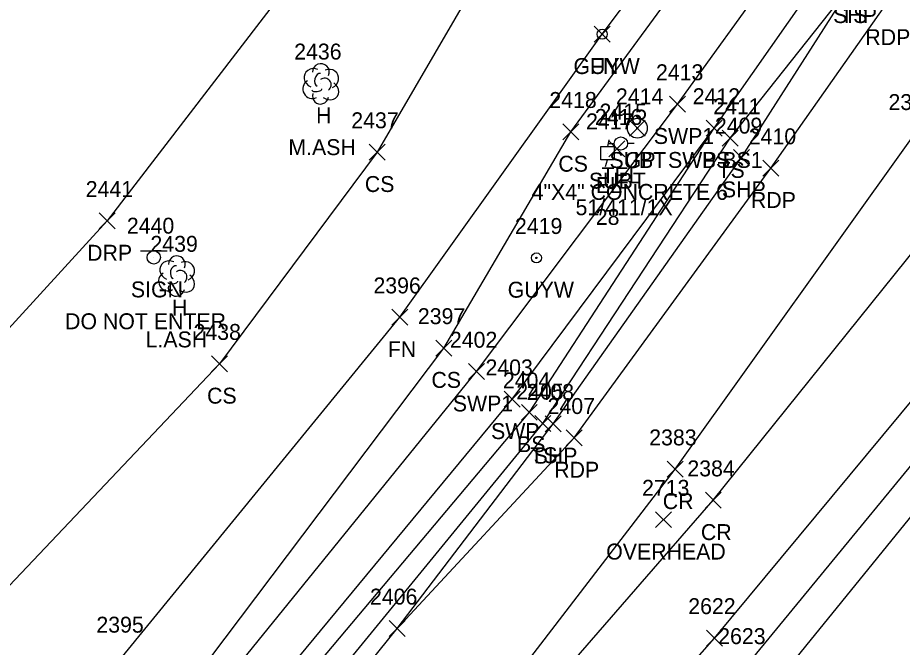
# Model space of a CAD drawing. Extents: x 1477930 to 1480780, y 774090 to 784647.
# Drawn here: x 1479285.9 to 1479397, y 774778.8 to 774857.9 of the extents above; entities that cross this region are included whole.
import ezdxf

# ---------------------------------------------------------------- set-up
doc = ezdxf.new("R2010")
doc.units = 0
for name, color, linetype in [('L_A', 7, 'Continuous'), ('L_C', 7, 'Continuous'), ('L_I', 7, 'Continuous'), ('L_TIC', 7, 'Continuous'), ('LELB', 7, 'Continuous'), ('LFNC', 7, 'Continuous'), ('LTD', 7, 'Continuous'), ('P_A', 7, 'Continuous'), ('P_I', 7, 'Continuous'), ('P_TIC', 7, 'Continuous'), ('PET', 7, 'Continuous'), ('PRC', 7, 'Continuous'), ('PSP', 7, 'Continuous'), ('R_A', 7, 'Continuous'), ('R_C', 7, 'Continuous'), ('R_I', 7, 'Continuous'), ('R_TIC', 7, 'Continuous'), ('RDP', 7, 'Continuous'), ('RGP', 7, 'Continuous'), ('RSW', 7, 'Continuous'), ('S_A', 7, 'Continuous'), ('S_C', 7, 'Continuous'), ('S_I', 7, 'Continuous'), ('SSGN', 7, 'Continuous'), ('U_A', 7, 'Continuous'), ('U_C', 7, 'Continuous'), ('U_I', 7, 'Continuous'), ('U_TIC', 7, 'Continuous'), ('UEPT', 7, 'Continuous'), ('UP', 7, 'Continuous'), ('UPGW', 7, 'Continuous')]:
    doc.layers.add(name, color=color, linetype=linetype)

msp = doc.modelspace()

# ---------------------------------------------------------------- linework, layer by layer
at = {"layer": 'L_TIC'}
for points in [[(1479358.32, 774854.82), (1479360.32, 774856.82)], [(1479360.32, 774854.82), (1479358.32, 774856.82)], [(1479372.39, 774843.03), (1479374.39, 774845.03)], [(1479374.39, 774843.03), (1479372.39, 774845.03)], [(1479354.38, 774842.56), (1479356.38, 774844.56)], [(1479356.38, 774842.56), (1479354.38, 774844.56)], [(1479374.4, 774841.78), (1479376.4, 774843.78)], [(1479376.4, 774841.78), (1479374.4, 774843.78)], [(1479330.08, 774840.01), (1479332.08, 774842.01)], [(1479332.08, 774840.01), (1479330.08, 774842.01)], [(1479332.92, 774819.28), (1479334.92, 774821.28)], [(1479334.92, 774819.28), (1479332.92, 774821.28)], [(1479338.44, 774815.42), (1479340.44, 774817.42)], [(1479340.44, 774815.42), (1479338.44, 774817.42)], [(1479310.27, 774813.44), (1479312.27, 774815.44)], [(1479312.27, 774813.44), (1479310.27, 774815.44)], [(1479349.18, 774807.35), (1479351.18, 774809.35)], [(1479351.18, 774807.35), (1479349.18, 774809.35)], [(1479350.88, 774805.96), (1479352.88, 774807.96)], [(1479352.88, 774805.96), (1479350.88, 774807.96)]]:
    msp.add_lwpolyline(points, dxfattribs=at)
at = {"layer": 'LELB'}
for points in [[(1479359.96, 774879.16), (1479348.06, 774870.2), (1479331.08, 774841.01), (1479311.27, 774814.44), (1479269.72, 774770.63), (1479258.46, 774742.87), (1479189.67, 774702.56), (1479160.61, 774665.86)], [(1478962.33, 774641.76), (1478963.97, 774605.71), (1478989.2, 774585.18), (1479035.48, 774565.64), (1479062.1, 774571.6), (1479071.52, 774575.06), (1479101.02, 774601.1), (1479154.98, 774641.54), (1479197.13, 774670.38), (1479247.47, 774711.89), (1479280.68, 774743.82), (1479306.08, 774772.18), (1479339.44, 774816.42), (1479355.38, 774843.56), (1479373.73, 774868.57)], [(1478740.27, 774421.37), (1478804.49, 774448.68), (1478839.51, 774461.41), (1478900.12, 774482.9), (1478933.76, 774495.55), (1478952.86, 774503.55), (1479014.49, 774533.68), (1479069.06, 774560.68), (1479112.01, 774585.56), (1479167.75, 774622.17), (1479210.47, 774656.8), (1479257.79, 774698.97), (1479291.85, 774733.88), (1479316.96, 774764.31), (1479351.88, 774806.96), (1479375.4, 774842.78), (1479390.8, 774862.22)], [(1479239.1, 774628.15), (1479242.92, 774638.24), (1479276.86, 774668.3), (1479306.94, 774697.73), (1479319.53, 774710.27), (1479351.31, 774740.09), (1479380.37, 774773.44), (1479412.56, 774813.05), (1479431.34, 774845.03)], [(1479014.49, 774533.68), (1479043.28, 774555.25), (1479065.32, 774566.41), (1479074.11, 774570.76), (1479108.86, 774587.86), (1479163.89, 774628.29), (1479207.81, 774659.29), (1479255.33, 774701.37), (1479289.44, 774735.89), (1479314.43, 774765.82), (1479350.18, 774808.35), (1479373.39, 774844.03)]]:
    msp.add_lwpolyline(points, dxfattribs=at)
at = {"layer": 'LFNC'}
msp.add_lwpolyline([(1478963.8, 774657.83), (1478978.61, 774653.25), (1478971.45, 774628.81), (1478963.97, 774605.71), (1479000.4, 774593.85), (1479046.12, 774579.13), (1479053.93, 774576.72), (1479097.31, 774607.25), (1479152.18, 774645.44), (1479192.1, 774673.94), (1479241.74, 774716.53), (1479274.15, 774749.58), (1479299.07, 774777.69), (1479333.92, 774820.28), (1479359.32, 774855.82), (1479370.21, 774870.3)], dxfattribs=at)
at = {"layer": 'LTD'}
for p, q in [((1479323.97, 774849.64), (1479323.97, 774849.64)), ((1479323.97, 774849.64), (1479323.97, 774849.64)), ((1479305.86, 774825.5), (1479305.86, 774825.5)), ((1479305.86, 774825.5), (1479305.86, 774825.5))]:
    msp.add_line(p, q, dxfattribs=at)
for centre in [(1479324.01, 774851.07), (1479305.91, 774826.93)]:
    msp.add_arc(centre, 1.05, 335.5272, 180.9563, dxfattribs=at)
for centre, major_axis, ratio, start_param, end_param in [((1479323.18, 774850.3), (1.21, -0.51), 0.895232, 1.570796, 4.712389), ((1479325.01, 774850.22), (-1.14, -0.48), 0.949671, 1.570796, 4.712389), ((1479323.76, 774850.09), (-0.208, -0.792), 0.645439, 3.141593, 6.283185), ((1479324.47, 774849.47), (-0.5, 0.667), 0.989748, 3.141593, 6.283185), ((1479322.88, 774848.93), (0.58, -1.04), 0.959034, 3.141593, 6.283185), ((1479324.97, 774848.8), (-1.09, 0.79), 0.841452, 1.570796, 4.712389), ((1479323.97, 774848.14), (0.26, 1.06), 0.942809, 1.570796, 4.712389), ((1479323.51, 774848.89), (-0.625, -0.083), 0.423636, 0, 3.141593), ((1479305.07, 774826.16), (1.21, -0.51), 0.895232, 1.570796, 4.712389), ((1479306.9, 774826.08), (-1.14, -0.48), 0.949671, 1.570796, 4.712389), ((1479304.78, 774824.79), (0.58, -1.04), 0.959034, 3.141593, 6.283185), ((1479305.65, 774825.96), (-0.208, -0.792), 0.645439, 3.141593, 6.283185), ((1479306.36, 774825.33), (-0.5, 0.667), 0.989748, 3.141593, 6.283185), ((1479305.41, 774824.75), (-0.625, -0.083), 0.423636, 0, 3.141593), ((1479306.86, 774824.66), (-1.09, 0.79), 0.841452, 1.570796, 4.712389), ((1479305.86, 774824), (0.26, 1.06), 0.942809, 1.570796, 4.712389)]:
    msp.add_ellipse(centre, major_axis=major_axis, ratio=ratio, start_param=start_param, end_param=end_param, dxfattribs=at)
at = {"layer": 'P_TIC'}
for points in [[(1479375.82, 774839.34), (1479377.82, 774841.34)], [(1479377.82, 774839.34), (1479375.82, 774841.34)], [(1479379.51, 774838), (1479381.51, 774840)], [(1479381.51, 774838), (1479379.51, 774840)], [(1479352.18, 774805.91), (1479354.18, 774807.91)], [(1479354.18, 774805.91), (1479352.18, 774807.91)], [(1479354.81, 774804.14), (1479356.81, 774806.14)], [(1479356.81, 774804.14), (1479354.81, 774806.14)], [(1479367.49, 774800.2), (1479369.49, 774802.2)], [(1479369.49, 774800.2), (1479367.49, 774802.2)], [(1479372.28, 774796.31), (1479374.28, 774798.31)], [(1479374.28, 774796.31), (1479372.28, 774798.31)], [(1479332.57, 774780.21), (1479334.57, 774782.21)], [(1479334.57, 774780.21), (1479332.57, 774782.21)], [(1479332.57, 774780.21), (1479334.57, 774782.21)], [(1479334.57, 774780.21), (1479332.57, 774782.21)], [(1479372.44, 774779.01), (1479374.44, 774781.01)], [(1479374.44, 774779.01), (1479372.44, 774781.01)]]:
    msp.add_lwpolyline(points, dxfattribs=at)
at = {"layer": 'PET'}
for points in [[(1479231.31, 774636.06), (1479272.54, 774672.78), (1479302.99, 774702.6), (1479344.22, 774746.86), (1479373.44, 774780.01), (1479405.23, 774818.27), (1479428.23, 774848.68), (1479447.93, 774875.75), (1479460.71, 774894.51), (1479479.69, 774925.18), (1479480.31, 774927.38), (1479493.45, 774951.2), (1479514.74, 775006.53), (1479531.7, 775055.13), (1479548.14, 775106.72), (1479553.83, 775125.43), (1479564.45, 775161.29), (1479573.74, 775193.3), (1479576.58, 775204.25), (1479585.43, 775238.68), (1479593.96, 775273.34), (1479599.4, 775295.6)], [(1479168.73, 774620.31), (1479212.4, 774655.38), (1479259.7, 774697.56), (1479293.15, 774732.73), (1479318.8, 774762.89), (1479333.57, 774781.21), (1479355.81, 774805.14), (1479380.51, 774839), (1479394.88, 774859.45), (1479419.72, 774898.43), (1479440.51, 774934.48), (1479462.36, 774978.06), (1479482.36, 775026.15), (1479497.52, 775065.91), (1479509.28, 775100.79), (1479510.93, 775118.31)]]:
    msp.add_lwpolyline(points, dxfattribs=at)
at = {"layer": 'PRC'}
for points in [[(1479194.24, 774620.68), (1479224.8, 774645.46), (1479270.23, 774685.77), (1479304.81, 774721.63), (1479337.5, 774760.88), (1479368.49, 774801.2), (1479398.58, 774843.3), (1479429.86, 774889.66)], [(1479304.81, 774721.63), (1479339.94, 774758.98), (1479373.28, 774797.31), (1479405.3, 774837.12), (1479437.9, 774882.86)]]:
    msp.add_lwpolyline(points, dxfattribs=at)
at = {"layer": 'PSP'}
for points in [[(1479333.57, 774781.21), (1479353.18, 774806.91), (1479376.82, 774840.34), (1479390.8, 774862.22), (1479415.7, 774900.26), (1479436.53, 774936.29), (1479458.59, 774979.44), (1479478.64, 775027.16), (1479495.22, 775066.68), (1479506.41, 775101.31), (1479509.16, 775114.37), (1479508.43, 775127.01)], [(1479234.45, 774632.83), (1479231.31, 774636.06), (1479275.79, 774669.49), (1479305.63, 774698.93), (1479347.8, 774743.57), (1479377.2, 774776.25), (1479409.48, 774815.47), (1479431.34, 774845.03), (1479437.58, 774844.49), (1479438.63, 774843.63)]]:
    msp.add_lwpolyline(points, dxfattribs=at)
at = {"layer": 'R_TIC'}
for points in [[(1479367.77, 774846.04), (1479369.77, 774848.04)], [(1479369.77, 774846.04), (1479367.77, 774848.04)], [(1479372.39, 774843.03), (1479374.39, 774845.03)], [(1479374.39, 774843.03), (1479372.39, 774845.03)], [(1479296.16, 774831.38), (1479298.16, 774833.38)], [(1479298.16, 774831.38), (1479296.16, 774833.38)], [(1479342.53, 774812.46), (1479344.53, 774814.46)], [(1479344.53, 774812.46), (1479342.53, 774814.46)], [(1479347.01, 774808.99), (1479349.01, 774810.99)], [(1479349.01, 774808.99), (1479347.01, 774810.99)]]:
    msp.add_lwpolyline(points, dxfattribs=at)
at = {"layer": 'RDP'}
msp.add_lwpolyline([(1479339.32, 774894.51), (1479323.7, 774866.97), (1479297.16, 774832.38), (1479261.24, 774793.14), (1479230.98, 774760.26), (1479216.66, 774770.36), (1479214.83, 774766.86), (1479218.05, 774749.14), (1479185.32, 774759.37)], dxfattribs=at)
at = {"layer": 'RGP'}
msp.add_line((1479363.74, 774844.02), (1479363.74, 774844.02), dxfattribs=at)
for radius in [1.25, 0.0833]:
    msp.add_circle((1479363.74, 774844.02), radius, dxfattribs=at)
at = {"layer": 'RSW'}
for points in [[(1479274.17, 774731.39), (1479308.42, 774770.17), (1479343.53, 774813.46), (1479368.77, 774847.04), (1479380.89, 774863.8), (1479383.37, 774867.44), (1479386.24, 774871.51), (1479407.11, 774905.13), (1479428.53, 774941.71), (1479450.08, 774982.66), (1479469.96, 775030.3), (1479484.01, 775070.5), (1479497.13, 775105.7)], [(1479277.58, 774728.25), (1479312.53, 774767.11), (1479348.01, 774809.99), (1479373.39, 774844.03), (1479387.54, 774864.22), (1479390.19, 774868.27), (1479411.38, 774902.61), (1479432.83, 774938.99), (1479454.5, 774980.05), (1479474.41, 775028.7), (1479489.03, 775068.75), (1479501.66, 775103.93)]]:
    msp.add_lwpolyline(points, dxfattribs=at)
at = {"layer": 'SSGN'}
for p, q in [((1479301.36, 774828.63), (1479304.69, 774828.63)), ((1479303.01, 774827.8), (1479303.01, 774827.8))]:
    msp.add_line(p, q, dxfattribs=at)
msp.add_circle((1479303.01, 774827.8), 0.833, dxfattribs=at)
at = {"layer": 'U_TIC'}
for points in [[(1479362.74, 774843.02), (1479364.74, 774845.02)], [(1479364.74, 774843.02), (1479362.74, 774845.02)], [(1479360.16, 774840.43), (1479362.16, 774842.43)], [(1479362.16, 774840.43), (1479360.16, 774842.43)], [(1479366.02, 774793.87), (1479368.02, 774795.87)], [(1479368.02, 774793.87), (1479366.02, 774795.87)]]:
    msp.add_lwpolyline(points, dxfattribs=at)
at = {"layer": 'UEPT'}
for p, q in [((1479360.16, 774842.54), (1479359.99, 774841.71)), ((1479359.16, 774840.04), (1479359.16, 774841.71)), ((1479359.16, 774841.71), (1479360.82, 774841.71)), ((1479360.82, 774841.71), (1479360.82, 774840.04)), ((1479359.99, 774840.88), (1479359.99, 774840.88)), ((1479360.82, 774840.04), (1479359.16, 774840.04)), ((1479359.74, 774839.21), (1479359.99, 774840.04))]:
    msp.add_line(p, q, dxfattribs=at)
at = {"layer": 'UP'}
for p, q in [((1479360.02, 774842.1), (1479360.85, 774842.1)), ((1479361.68, 774842.1), (1479361.68, 774842.1)), ((1479363.35, 774842.1), (1479362.52, 774842.1)), ((1479362.52, 774842.1), (1479362.52, 774842.1)), ((1479363.35, 774842.1), (1479363.35, 774842.1))]:
    msp.add_line(p, q, dxfattribs=at)
msp.add_circle((1479361.68, 774842.1), 0.833, dxfattribs=at)
at = {"layer": 'UPGW'}
for centre, radius in [((1479359.32, 774855.82), 0.625), ((1479359.32, 774855.82), 0.0833), ((1479351.07, 774827.74), 0.625), ((1479351.07, 774827.74), 0.0833)]:
    msp.add_circle(centre, radius, dxfattribs=at)

# ---------------------------------------------------------------- texts
at = {"layer": 'L_A'}
for s, p in [('TS', (1479389.21, 774857.22)), ('FN', (1479357.8, 774850.82)), ('H', (1479323.4, 774844.64)), ('CS', (1479353.82, 774838.56)), ('BS', (1479371.83, 774839.03)), ('TS', (1479373.81, 774837.78)), ('CS', (1479329.52, 774836.01)), ('H', (1479305.3, 774820.5)), ('FN', (1479332.4, 774815.28)), ('CS', (1479337.88, 774811.42)), ('CS', (1479309.71, 774809.44)), ('BS', (1479348.63, 774803.35)), ('TS', (1479350.29, 774801.96))]:
    msp.add_text(s, height=2, dxfattribs=at).set_placement(p)
at = {"layer": 'L_C'}
for s, p in [('M.ASH', (1479319.92, 774840.64)), ('L.ASH', (1479301.99, 774816.5))]:
    msp.add_text(s, height=2, dxfattribs=at).set_placement(p)
at = {"layer": 'L_I'}
for s, p in [('2436', (1479320.65, 774852.64)), ('2418', (1479352.69, 774846.56)), ('2412', (1479370.69, 774847.03)), ('2411', (1479373.27, 774845.78)), ('2437', (1479327.82, 774844.01)), ('2439', (1479302.6, 774828.5)), ('2396', (1479330.6, 774823.28)), ('2397', (1479336.18, 774819.42)), ('2438', (1479308.01, 774817.44)), ('2404', (1479346.85, 774811.35)), ('2405', (1479348.54, 774809.96)), ('2395', (1479295.81, 774780.69))]:
    msp.add_text(s, height=2, dxfattribs=at).set_placement(p)
at = {"layer": 'P_A'}
for s, p in [('SHP', (1479388.33, 774857.22)), ('RDP', (1479392.37, 774854.45)), ('SHP', (1479374.36, 774835.34)), ('RDP', (1479378, 774834)), ('SHP', (1479350.71, 774801.91)), ('RDP', (1479353.3, 774800.14)), ('CR', (1479366.93, 774796.2)), ('CR', (1479371.72, 774792.31))]:
    msp.add_text(s, height=2, dxfattribs=at).set_placement(p)
at = {"layer": 'P_I'}
for s, p in [('2386', (1479395.27, 774846.3)), ('2409', (1479373.48, 774843.34)), ('2410', (1479377.73, 774842)), ('2408', (1479349.84, 774809.91)), ('2407', (1479352.47, 774808.14)), ('2383', (1479365.23, 774804.2)), ('2384', (1479370.02, 774800.31)), ('2406', (1479330.17, 774784.21)), ('2406', (1479330.17, 774784.21)), ('2622', (1479370.13, 774783.01)), ('2623', (1479373.89, 774779.25))]:
    msp.add_text(s, height=2, dxfattribs=at).set_placement(p)
at = {"layer": 'R_A'}
for s, p in [('SWP1', (1479365.81, 774842.04)), ('GP', (1479362.17, 774839.02)), ('SWP BS1', (1479367.59, 774839.03)), ('DRP', (1479294.65, 774827.38)), ('SWP1', (1479340.57, 774808.46)), ('SWP', (1479345.37, 774804.99))]:
    msp.add_text(s, height=2, dxfattribs=at).set_placement(p)
at = {"layer": 'R_C'}
msp.add_text('4"X4" CONCRETE 6', height=2, dxfattribs=at).set_placement((1479350.47, 774835.02))
at = {"layer": 'R_I'}
for s, p in [('2413', (1479366.08, 774850.04)), ('2414', (1479361.05, 774847.02)), ('2412', (1479370.69, 774847.03)), ('2441', (1479294.47, 774835.38)), ('2402', (1479340.2, 774816.46)), ('2403', (1479344.67, 774812.99))]:
    msp.add_text(s, height=2, dxfattribs=at).set_placement(p)
at = {"layer": 'S_A'}
msp.add_text('SIGN', height=2, dxfattribs=at).set_placement((1479300.15, 774822.78))
at = {"layer": 'S_C'}
msp.add_text('DO NOT ENTER', height=2, dxfattribs=at).set_placement((1479291.88, 774818.78))
at = {"layer": 'S_I'}
msp.add_text('2440', height=2, dxfattribs=at).set_placement((1479299.64, 774830.78))
at = {"layer": 'U_A'}
for s, p in [('GUYW', (1479355.72, 774850.82)), ('SUBT', (1479360.24, 774839.02)), ('TEL', (1479359.24, 774837.1)), ('SUBT', (1479357.66, 774836.43)), ('EL', (1479358.52, 774835.88)), ('GUYW', (1479347.46, 774822.74)), ('OVERHEAD', (1479359.83, 774789.87))]:
    msp.add_text(s, height=2, dxfattribs=at).set_placement(p)
at = {"layer": 'U_C'}
for s, p in [('51/411/1X', (1479355.98, 774833.1)), ('28', (1479358.52, 774831.88))]:
    msp.add_text(s, height=2, dxfattribs=at).set_placement(p)
at = {"layer": 'U_I'}
for s, p in [('2414', (1479361.05, 774847.02)), ('2415', (1479358.99, 774845.1)), ('2417', (1479357.3, 774843.88)), ('2416', (1479358.41, 774844.43)), ('2419', (1479348.37, 774830.74)), ('2713', (1479364.33, 774797.87))]:
    msp.add_text(s, height=2, dxfattribs=at).set_placement(p)

doc.saveas('drawing.dxf')
